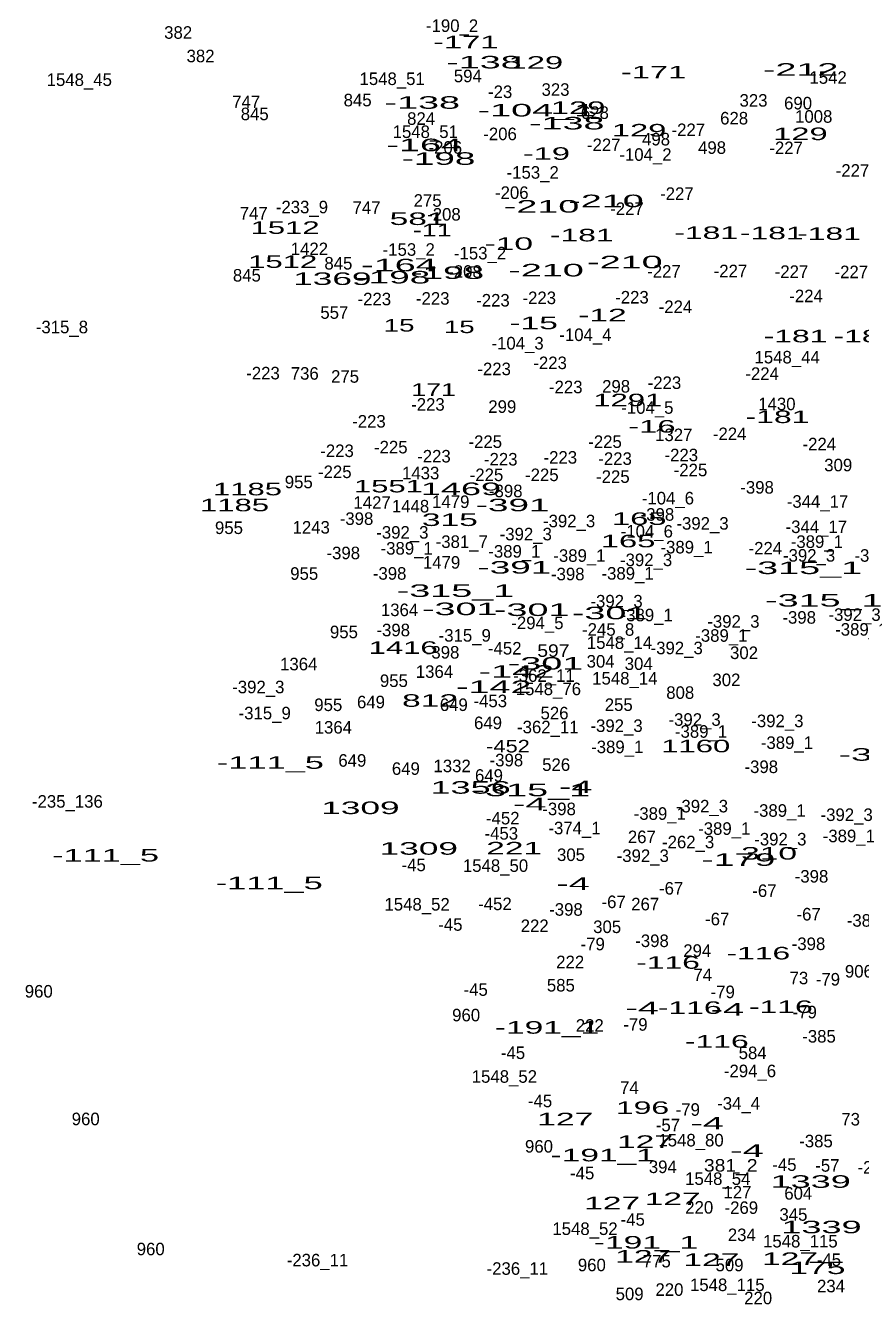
# Model space of a CAD drawing. Extents: x -660434 to -656144, y -997850 to -994016.
# Drawn here: x -658831.7 to -658565.3, y -996494 to -996086 of the extents above; entities that cross this region are included whole.
import ezdxf
from ezdxf.enums import TextEntityAlignment as Align

# ---------------------------------------------------------------- set-up
doc = ezdxf.new("R2010")
doc.units = 0
doc.header["$LTSCALE"] = 1.6
doc.layers.add('24', color=7, linetype='Continuous')

msp = doc.modelspace()

# ---------------------------------------------------------------- texts
at = {"layer": '24'}
for s, p in [('382', (-658782.977, -996090.25)), ('-190_2', (-658695.586, -996088.08)), ('382', (-658775.827, -996097.75)), ('1548_45', (-658814.517, -996105.32)), ('1548_51', (-658714.706, -996105.01)), ('594', (-658690.567, -996104.12)), ('1542', (-658575.624, -996104.61)), ('-23', (-658680.245, -996109.16)), ('323', (-658662.587, -996108.45)), ('747', (-658761.273, -996112.39)), ('845', (-658725.721, -996111.81)), ('628', (-658650.033, -996115.82)), ('323', (-658599.417, -996111.91)), ('690', (-658585.212, -996112.79)), ('845', (-658758.551, -996116.23)), ('824', (-658705.471, -996117.71)), ('628', (-658605.613, -996117.59)), ('1008', (-658580.218, -996117.04)), ('1548_51', (-658704.146, -996121.91)), ('-206', (-658680.284, -996122.6)), ('-227', (-658620.231, -996121.29)), ('-206', (-658697.754, -996126.92)), ('-227', (-658647.201, -996126.09)), ('498', (-658630.517, -996124.28)), ('498', (-658612.657, -996126.97)), ('-227', (-658589.021, -996127.05)), ('-104_2', (-658633.894, -996129.19)), ('-153_2', (-658669.866, -996134.89)), ('-227', (-658567.841, -996134.26)), ('275', (-658703.393, -996143.84)), ('-206', (-658676.534, -996141.33)), ('-227', (-658623.871, -996141.65)), ('747', (-658758.873, -996147.92)), ('-233_9', (-658743.488, -996145.93)), ('747', (-658722.873, -996146.1)), ('-208', (-658698.189, -996148.25)), ('-227', (-658639.811, -996146.45)), ('1422', (-658741.114, -996159.28)), ('-153_2', (-658709.416, -996159.48)), ('-153_2', (-658686.666, -996160.63)), ('845', (-658731.861, -996163.86)), ('845', (-658761.051, -996167.7)), ('-208', (-658691.469, -996166.5)), ('-227', (-658628.001, -996166.43)), ('-227', (-658606.781, -996166.33)), ('-227', (-658587.301, -996166.53)), ('-227', (-658568.231, -996166.62)), ('-223', (-658720.385, -996175.27)), ('-223', (-658701.755, -996175.08)), ('-223', (-658682.555, -996175.66)), ('-223', (-658667.775, -996174.89)), ('-223', (-658638.205, -996174.7)), ('-224', (-658582.659, -996174.28)), ('557', (-658733.153, -996179.58)), ('-224', (-658624.319, -996177.74)), ('-315_8', (-658820.056, -996184.2)), ('-104_4', (-658653.049, -996186.67)), ('-104_3', (-658674.694, -996189.36)), ('-223', (-658664.315, -996195.63)), ('1548_44', (-658588.691, -996193.81)), ('-223', (-658755.905, -996198.9)), ('736', (-658742.588, -996199)), ('275', (-658729.733, -996199.97)), ('-223', (-658682.175, -996197.56)), ('-224', (-658596.669, -996199.06)), ('-223', (-658659.325, -996203.32)), ('298', (-658643.263, -996203.11)), ('-223', (-658627.835, -996201.97)), ('-223', (-658703.295, -996208.89)), ('299', (-658679.568, -996209.58)), ('1430', (-658591.968, -996208.74)), ('-104_5', (-658633.294, -996209.88)), ('-223', (-658722.115, -996214.27)), ('-225', (-658685.005, -996220.78)), ('-225', (-658646.795, -996220.78)), ('1327', (-658624.866, -996218.6)), ('-224', (-658607.039, -996218.27)), ('-224', (-658578.439, -996221.54)), ('-223', (-658732.285, -996223.68)), ('-225', (-658715.145, -996222.51)), ('-223', (-658701.375, -996225.41)), ('-223', (-658661.055, -996225.79)), ('-223', (-658622.465, -996225.02)), ('-223', (-658680.065, -996226.37)), ('-223', (-658643.585, -996226.17)), ('-225', (-658619.525, -996229.81)), ('309', (-658572.397, -996228.23)), ('955', (-658744.493, -996233.63)), ('-225', (-658733.005, -996230.39)), ('1433', (-658705.604, -996230.78)), ('-225', (-658684.615, -996231.35)), ('-225', (-658666.955, -996231.35)), ('-225', (-658644.295, -996231.92)), ('-398', (-658678.46, -996236.49)), ('-398', (-658598.29, -996235.34)), ('1427', (-658721.11, -996240.19)), ('1448', (-658708.839, -996241.34)), ('1479', (-658696.015, -996239.93)), ('-104_6', (-658626.74, -996238.79)), ('-344_17', (-658578.999, -996239.85)), ('-398', (-658726.07, -996245.32)), ('-392_3', (-658658.248, -996246.08)), ('-398', (-658630.07, -996243.98)), ('955', (-658766.763, -996248.23)), ('1243', (-658740.524, -996248.09)), ('-392_3', (-658711.448, -996249.7)), ('-392_3', (-658672.068, -996250.25)), ('-104_6', (-658633.46, -996249.35)), ('-392_3', (-658615.688, -996246.84)), ('-344_17', (-658579.389, -996247.92)), ('-381_7', (-658692.492, -996252.67)), ('-389_1', (-658620.782, -996254.41)), ('-389_1', (-658579.212, -996252.66)), ('-398', (-658730.3, -996256.27)), ('-389_1', (-658710.072, -996254.79)), ('-389_1', (-658675.702, -996255.75)), ('-389_1', (-658654.962, -996257.1)), ('-392_3', (-658633.688, -996258.47)), ('-224', (-658595.659, -996254.76)), ('-392_3', (-658581.688, -996257.04)), ('-389_1', (-658558.902, -996257.07)), ('1479', (-658698.945, -996259.28)), ('955', (-658742.763, -996262.83)), ('-398', (-658715.51, -996262.8)), ('-398', (-658658.68, -996262.99)), ('-389_1', (-658639.602, -996262.78)), ('1364', (-658712.35, -996274.42)), ('-392_3', (-658643.118, -996271.65)), ('-294_5', (-658668.362, -996278.56)), ('-389_1', (-658633.492, -996276.06)), ('-392_3', (-658605.828, -996278.11)), ('-398', (-658584.85, -996276.83)), ('-392_3', (-658567.188, -996275.93)), ('955', (-658730.093, -996281.46)), ('-398', (-658714.36, -996280.85)), ('-315_9', (-658691.542, -996282.56)), ('-245_8', (-658645.797, -996280.67)), ('-389_1', (-658609.682, -996282.59)), ('-389_1', (-658565.042, -996280.65)), ('-452', (-658678.789, -996286.66)), ('1548_14', (-658642.181, -996284.88)), ('-392_3', (-658623.928, -996286.57)), ('-398', (-658698.62, -996287.96)), ('304', (-658648.205, -996290.83)), ('302', (-658602.451, -996288.11)), ('1364', (-658744.51, -996291.71)), ('1364', (-658701.21, -996294.11)), ('304', (-658636.055, -996291.6)), ('-392_3', (-658757.408, -996299.02)), ('955', (-658714.153, -996297.02)), ('-362_11', (-658666.295, -996295.38)), ('1548_14', (-658640.471, -996296.24)), ('302', (-658608.071, -996296.74)), ('-453', (-658683.399, -996303.46)), ('1548_76', (-658664.863, -996299.63)), ('808', (-658622.801, -996300.81)), ('-315_9', (-658755.362, -996307.34)), ('955', (-658735.083, -996304.7)), ('649', (-658721.463, -996303.82)), ('649', (-658695.043, -996304.68)), ('526', (-658662.903, -996307.34)), ('255', (-658642.417, -996304.68)), ('649', (-658684.123, -996310.46)), ('-392_3', (-658643.118, -996311.37)), ('-392_3', (-658618.218, -996309.4)), ('-392_3', (-658591.808, -996309.84)), ('1364', (-658733.47, -996311.88)), ('-362_11', (-658665.045, -996311.8)), ('-389_1', (-658616.162, -996313.21)), ('-389_1', (-658642.902, -996318.13)), ('-389_1', (-658588.762, -996316.78)), ('649', (-658727.413, -996322.45)), ('-398', (-658678.26, -996322.34)), ('526', (-658662.383, -996323.79)), ('649', (-658710.333, -996325.05)), ('1332', (-658695.57, -996324.2)), ('649', (-658683.813, -996327.25)), ('-398', (-658596.95, -996324.47)), ('-235_136', (-658818.311, -996335.52)), ('-398', (-658661.45, -996337.91)), ('-389_1', (-658629.312, -996339.39)), ('-392_3', (-658615.878, -996337.03)), ('-389_1', (-658591.102, -996338.42)), ('-392_3', (-658569.708, -996339.77)), ('-452', (-658679.419, -996340.86)), ('-374_1', (-658656.526, -996344.01)), ('-389_1', (-658608.762, -996344.18)), ('-453', (-658679.879, -996345.72)), ('267', (-658635.048, -996346.83)), ('-392_3', (-658590.868, -996347.56)), ('-389_1', (-658569.012, -996346.53)), ('-262_3', (-658620.278, -996348.48)), ('-45', (-658707.839, -996355.77)), ('1548_50', (-658681.726, -996356)), ('305', (-658657.651, -996352.53)), ('-392_3', (-658634.748, -996352.84)), ('-398', (-658580.92, -996359.42)), ('-67', (-658625.705, -996363.23)), ('-67', (-658595.945, -996364)), ('1548_52', (-658706.742, -996368.33)), ('-452', (-658681.909, -996368.2)), ('-67', (-658644.045, -996367.55)), ('267', (-658633.978, -996368.27)), ('-398', (-658659.26, -996369.98)), ('-67', (-658581.835, -996371.49)), ('-45', (-658696.129, -996374.78)), ('222', (-658669.237, -996375.19)), ('305', (-658646.111, -996375.51)), ('-67', (-658611.015, -996373.03)), ('-381_6', (-658561.342, -996373.48)), ('-398', (-658631.8, -996379.97)), ('-398', (-658581.88, -996380.93)), ('-79', (-658650.725, -996381.02)), ('294', (-658617.367, -996383.1)), ('222', (-658657.907, -996386.72)), ('74', (-658615.617, -996390.82)), ('73', (-658584.943, -996391.85)), ('-79', (-658575.695, -996392.25)), ('906', (-658565.802, -996389.7)), ('960', (-658827.442, -996396.08)), ('-45', (-658688.059, -996395.53)), ('585', (-658660.887, -996394.15)), ('-79', (-658609.245, -996396.28)), ('960', (-658691.102, -996403.67)), ('-79', (-658583.085, -996402.72)), ('222', (-658651.667, -996406.98)), ('-79', (-658637.085, -996406.66)), ('-385', (-658578.525, -996410.44)), ('-45', (-658676.159, -996415.69)), ('584', (-658599.701, -996415.72)), ('-294_6', (-658600.548, -996421.49)), ('1548_52', (-658678.902, -996423.26)), ('74', (-658639.037, -996426.83)), ('-45', (-658667.519, -996431.06)), ('-79', (-658620.385, -996433.8)), ('-34_4', (-658604.171, -996431.83)), ('960', (-658812.472, -996436.8)), ('73', (-658568.433, -996436.89)), ('-57', (-658626.731, -996438.76)), ('960', (-658667.862, -996445.54)), ('1548_80', (-658619.356, -996443.57)), ('-385', (-658579.485, -996443.86)), ('-45', (-658654.079, -996454.07)), ('394', (-658628.367, -996452.07)), ('-45', (-658589.569, -996451.37)), ('-57', (-658575.851, -996451.63)), ('-269', (-658560.885, -996452.23)), ('1548_54', (-658610.827, -996455.86)), ('127', (-658604.551, -996460.17)), ('604', (-658585.141, -996460.54)), ('220', (-658616.741, -996465.01)), ('-269', (-658603.315, -996465.1)), ('-45', (-658637.949, -996468.86)), ('345', (-658586.691, -996467.27)), ('1548_52', (-658653.182, -996471.82)), ('234', (-658603.161, -996473.77)), ('960', (-658791.732, -996478.29)), ('1548_115', (-658584.48, -996475.8)), ('-236_11', (-658738.515, -996481.83)), ('775', (-658630.279, -996482.15)), ('-45', (-658575.359, -996481.72)), ('-236_11', (-658674.765, -996484.52)), ('960', (-658651.002, -996483.38)), ('509', (-658607.077, -996483.39)), ('1548_115', (-658607.79, -996489.71)), ('234', (-658574.701, -996490.11)), ('509', (-658638.947, -996492.61)), ('220', (-658626.251, -996491.23)), ('220', (-658597.931, -996493.91))]:
    msp.add_text(s, height=4, dxfattribs=at).set_placement(p, align=Align.CENTER)
for s, width, p in [('-171', 1.95, (-658691.221, -996093.29)), ('-138', 2.25, (-658685.421, -996099.72)), ('129', 1.95, (-658668.863, -996099.82)), ('-171', 1.95, (-658631.321, -996102.89)), ('-212', 2.25, (-658584.401, -996102.05)), ('-138', 2.25, (-658705.111, -996112.59)), ('-104_1', 2.25, (-658668.719, -996115.04)), ('129', 1.95, (-658655.363, -996114.23)), ('-138', 2.25, (-658659.021, -996119.18)), ('129', 1.95, (-658635.923, -996121.43)), ('129', 1.95, (-658584.473, -996122.58)), ('-164', 2.25, (-658704.491, -996126.11)), ('-198', 2.2, (-658699.935, -996130.47)), ('-19', 1.95, (-658665.505, -996128.87)), ('-210', 2.25, (-658646.507, -996143.98)), ('-210', 2.25, (-658667.057, -996145.7)), ('1512', 1.85, (-658748.864, -996152.49)), ('581', 2, (-658706.587, -996149.66)), ('-11', 1.6, (-658701.887, -996153.28)), ('-181', 1.9, (-658654.217, -996154.88)), ('-181', 1.9, (-658614.517, -996154.11)), ('-181', 1.9, (-658593.597, -996154.2)), ('-181', 1.9, (-658575.347, -996154.4)), ('-10', 2, (-658677.487, -996157.59)), ('1512', 1.85, (-658749.634, -996163.34)), ('-164', 2.25, (-658712.561, -996164.43)), ('-210', 2.25, (-658640.467, -996163.47)), ('1369', 2.1, (-658733.787, -996168.79)), ('-198', 2.2, (-658714.335, -996168.31)), ('-198', 2.2, (-658697.145, -996166.87)), ('-210', 2.25, (-658665.617, -996166.06)), ('-12', 2, (-658647.621, -996180.39)), ('15', 1.65, (-658712.497, -996183.65)), ('15', 1.65, (-658693.297, -996184.13)), ('-15', 2, (-658669.571, -996182.9)), ('-181', 1.9, (-658586.017, -996187.09)), ('-181', 1.9, (-658563.747, -996187.09)), ('171', 1.6, (-658701.479, -996204.16)), ('1291', 1.85, (-658639.529, -996207.47)), ('-181', 1.9, (-658591.767, -996212.83)), ('-16', 1.95, (-658631.815, -996215.87)), ('1185', 1.85, (-658760.854, -996235.89)), ('1551', 1.85, (-658715.894, -996234.95)), ('1469', 2.15, (-658692.753, -996235.81)), ('1185', 1.85, (-658764.984, -996240.98)), ('-391', 2.2, (-658676.285, -996240.97)), ('315', 2, (-658696.297, -996245.67)), ('165', 1.95, (-658635.883, -996245.32)), ('165', 1.95, (-658639.433, -996252.47)), ('-391', 2.2, (-658675.715, -996260.85)), ('-315_1', 2.25, (-658583.527, -996261)), ('-315_1', 2.25, (-658694.507, -996268.29)), ('-301', 2.25, (-658693.147, -996274.1)), ('-301', 2.25, (-658670.197, -996274.38)), ('-315_1', 2.25, (-658576.997, -996271.37)), ('-301', 2.25, (-658645.337, -996275.43)), ('1416', 1.85, (-658711.195, -996286.45)), ('597', 1.15, (-658663.27, -996287.41)), ('-142', 2.25, (-658675.086, -996294.07)), ('-301', 2.25, (-658665.787, -996291.48)), ('-142', 2.25, (-658682.286, -996298.95)), ('812', 2, (-658702.627, -996303.34)), ('-452', 1.3, (-658677.75, -996317.9)), ('1160', 1.85, (-658617.865, -996317.85)), ('-111_5', 2.05, (-658753.544, -996323.12)), ('-315_1', 2.25, (-658553.567, -996320.54)), ('1356', 2.15, (-658689.673, -996331.06)), ('-315_1', 2.25, (-658670.307, -996331.87)), ('-4', 2.25, (-658656.15, -996330.85)), ('1309', 2.1, (-658724.829, -996337.56)), ('-4', 2.25, (-658670.84, -996336.35)), ('1309', 2.1, (-658706.209, -996350.52)), ('221', 2, (-658675.787, -996350.43)), ('310', 2, (-658594.464, -996352.07)), ('-111_5', 2.05, (-658806.154, -996352.7)), ('-179', 2.2, (-658604.239, -996354.07)), ('-111_5', 2.05, (-658753.924, -996361.54)), ('-4', 2.25, (-658657.02, -996361.77)), ('-116', 1.9, (-658597.891, -996383.92)), ('-116', 1.9, (-658626.701, -996386.89)), ('-116', 1.9, (-658619.781, -996401.3)), ('-116', 1.9, (-658590.691, -996401.01)), ('-4', 2.25, (-658634.96, -996401.4)), ('-4', 2.25, (-658607.79, -996401.87)), ('-191_1', 2, (-658665.309, -996407.61)), ('-116', 1.9, (-658611.141, -996412.06)), ('196', 1.9, (-658634.837, -996433.21)), ('127', 2, (-658659.493, -996436.83)), ('-4', 2.25, (-658614.22, -996438.15)), ('127', 2, (-658634.053, -996444.03)), ('-191_1', 2, (-658647.539, -996448.33)), ('-4', 2.25, (-658601.55, -996446.89)), ('381_2', 1.15, (-658606.69, -996451.6)), ('1339', 2.15, (-658581.183, -996456.77)), ('127', 2, (-658625.223, -996462.28)), ('127', 2, (-658644.523, -996463.62)), ('1339', 2.15, (-658577.733, -996471.27)), ('-191_1', 2, (-658633.719, -996476.15)), ('127', 2, (-658634.633, -996480.62)), ('127', 2, (-658612.843, -996481.68)), ('127', 2, (-658587.783, -996481.39)), ('175', 2, (-658579.033, -996484.28))]:
    msp.add_text(s, height=4, dxfattribs=dict(at, width=width)).set_placement(p, align=Align.CENTER)

doc.saveas('drawing.dxf')
